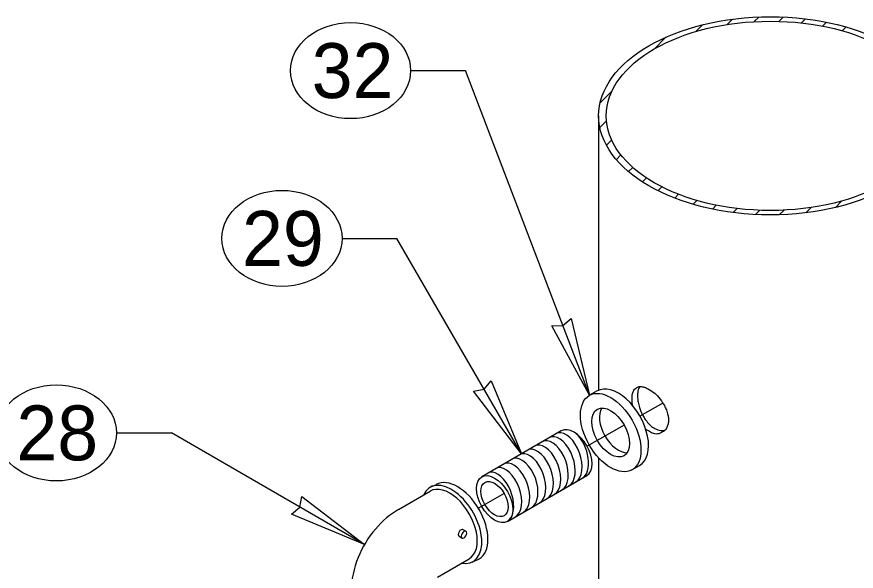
# Model space of a CAD drawing. Extents: x 99862 to 104211, y 98939 to 102076.
# Drawn here: x 101491.1 to 101735.6, y 101139.5 to 101301.1 of the extents above; entities that cross this region are included whole.
import ezdxf

# ---------------------------------------------------------------- set-up
doc = ezdxf.new("R2010")
doc.units = 0
for name, color, linetype in [('Level 1', 7, 'Continuous'), ('Level 12', 7, 'Continuous'), ('Level 15', 7, 'Continuous'), ('Level 16', 7, 'Continuous'), ('Level 2', 7, 'Continuous'), ('Level 20', 7, 'Continuous'), ('Level 28', 7, 'Continuous'), ('Level 29', 7, 'Continuous'), ('Level 30', 7, 'Continuous')]:
    doc.layers.add(name, color=color, linetype=linetype)

msp = doc.modelspace()

# ---------------------------------------------------------------- linework, layer by layer
at = {"layer": 'Level 1'}
msp.add_line((101671.69, 101193.07), (101671.69, 101193.07), dxfattribs=at)
for major_axis in [(50, 0), (47.77, 0)]:
    msp.add_ellipse((101710.6, 101272.27), major_axis=major_axis, ratio=0.57735, dxfattribs=at)
for centre, start_param, end_param in [((101650.96, 101172.59), 3.242095, 6.183178), ((101652.84, 101173.67), 3.242095, 5.457347), ((101646.93, 101170.26), 3.242095, 6.183178), ((101648.96, 101171.43), 3.242095, 6.183178), ((101642.6, 101167.76), 3.242095, 6.183178), ((101644.73, 101168.99), 3.242095, 6.183178), ((101638.1, 101165.16), 3.242095, 6.183178), ((101640.36, 101166.46), 3.242095, 6.183178), ((101633.35, 101162.42), 3.242095, 6.183178), ((101635.68, 101163.76), 3.242095, 6.183178), ((101631.03, 101161.08), 3.397612, 6.183178), ((101631.03, 101161.08), 3.242095, 3.243786)]:
    msp.add_ellipse(centre, major_axis=(-2.6, 7.2), ratio=0.565545, start_param=start_param, end_param=end_param, dxfattribs=at)
for points in [[(101670.54, 101187.8), (101670.41, 101188.48), (101670.34, 101189.14), (101670.34, 101190.55), (101670.45, 101191.26), (101670.91, 101192.39), (101671.25, 101192.81), (101672.13, 101193.32), (101672.66, 101193.4), (101673.87, 101193.24), (101674.55, 101192.98), (101676.62, 101191.78), (101678.1, 101190.38), (101679.73, 101187.93), (101680.17, 101187.05), (101680.78, 101185.3), (101680.94, 101184.44), (101680.94, 101182.82), (101680.78, 101182.09), (101680.18, 101180.87), (101679.73, 101180.39), (101678.11, 101179.45), (101676.64, 101179.52), (101675.24, 101180.33), (101674.92, 101180.52), (101674.62, 101180.73), (101674.32, 101180.98)], [(101672.6, 101193.34), (101672.17, 101192.72), (101671.94, 101191.79), (101671.94, 101189.88), (101672.05, 101188.98), (101672.5, 101187.14), (101672.84, 101186.21), (101673.72, 101184.44), (101674.25, 101183.62), (101675.45, 101182.22), (101676.13, 101181.65), (101677.87, 101180.64), (101678.97, 101180.45), (101679.92, 101180.66)]]:
    msp.add_open_spline(points, degree=3, dxfattribs=at)
at = {"layer": 'Level 12'}
for p, q in [((101698.03, 101298.88), (101699.58, 101300.43)), ((101705.94, 101299.72), (101707.27, 101301.05)), ((101713.11, 101299.81), (101714.33, 101301.04)), ((101719.71, 101299.35), (101720.87, 101300.5)), ((101725.84, 101298.41), (101726.97, 101299.53)), ((101688.93, 101296.85), (101690.87, 101298.79)), ((101731.56, 101297.05), (101732.65, 101298.15)), ((101676.73, 101291.72), (101680.18, 101295.17)), ((101661.08, 101276.07), (101664.49, 101279.48)), ((101660.6, 101272.27), (101660.6, 101192.31)), ((101660.99, 101268.91), (101662.9, 101270.82)), ((101662.89, 101263.74), (101664.4, 101265.25)), ((101665.76, 101259.54), (101667.1, 101260.88)), ((101669.31, 101256.02), (101670.54, 101257.25)), ((101673.39, 101253.03), (101674.55, 101254.18)), ((101677.9, 101250.47), (101679.02, 101251.58)), ((101682.8, 101248.29), (101683.91, 101249.4)), ((101688.1, 101246.52), (101689.2, 101247.62)), ((101693.76, 101245.11), (101694.88, 101246.23)), ((101720.97, 101244.04), (101722.5, 101245.57)), ((101729.57, 101245.57), (101731.47, 101247.47)), ((101699.83, 101244.11), (101700.98, 101245.26)), ((101706.32, 101243.53), (101707.54, 101244.75)), ((101713.33, 101243.47), (101714.66, 101244.8)), ((101660.6, 101172.62), (101660.6, 100999.47))]:
    msp.add_line(p, q, dxfattribs=at)
at = {"layer": 'Level 15'}
for p, q in [((101605.83, 101285.45), (101621.83, 101285.45)), ((101657.92, 101190.82), (101621.83, 101285.45)), ((101585.85, 101236.55), (101601.85, 101236.55)), ((101638.11, 101173.74), (101601.85, 101236.55)), ((101679.31, 101188.55), (101672.64, 101184.74)), ((101668.08, 101182.13), (101657.26, 101175.95)), ((101520.12, 101179.86), (101536.12, 101179.86)), ((101592.41, 101147.36), (101536.12, 101179.86)), ((101633.1, 101162.19), (101625.57, 101157.89))]:
    msp.add_line(p, q, dxfattribs=at)
for points in [[(101657.92, 101190.82), (101647, 101211.08), (101650.16, 101211.16), (101652.58, 101213.21)], [(101638.11, 101173.74), (101624.11, 101192.02), (101627.22, 101192.6), (101629.28, 101195)], [(101592.41, 101147.36), (101571.15, 101156.19), (101573.56, 101158.25), (101574.13, 101161.36)]]:
    msp.add_lwpolyline(points, close=True, dxfattribs=at)
at = {"layer": 'Level 16'}
for p, q in [((101621.07, 101151.68), (101621.93, 101151.18)), ((101619.94, 101149.72), (101620.81, 101149.22))]:
    msp.add_line(p, q, dxfattribs=at)
msp.add_ellipse((101620.51, 101150.7), major_axis=(-0.566, -0.98), ratio=0.57735, start_param=3.150736, end_param=6.274144, dxfattribs=at)
at = {"layer": 'Level 2'}
msp.add_ellipse((101621.37, 101150.2), major_axis=(-0.566, -0.98), ratio=0.57735, start_param=0.009244, end_param=6.292227, dxfattribs=at)
at = {"layer": 'Level 20'}
for centre in [(101588.33, 101285.45), (101568.35, 101236.55), (101502.62, 101179.86)]:
    msp.add_ellipse(centre, major_axis=(-17.5, 0), ratio=0.8, dxfattribs=at)
at = {"layer": 'Level 28'}
for p, q in [((101660.14, 101192.08), (101657.92, 101190.82)), ((101670.32, 101169.11), (101672.54, 101170.37))]:
    msp.add_line(p, q, dxfattribs=at)
for major_axis, start_param, end_param in [((6.2, -10.85), 0, 3.141593), ((3.88, -6.78), 3.428349, 5.996429)]:
    msp.add_ellipse((101666.34, 101181.23), major_axis=major_axis, ratio=0.57735, start_param=start_param, end_param=end_param, dxfattribs=at)
for major_axis in [(-6.2, 10.85), (-3.88, 6.78)]:
    msp.add_ellipse((101664.12, 101179.96), major_axis=major_axis, ratio=0.57735, dxfattribs=at)
at = {"layer": 'Level 29'}
for p, q in [((101611.52, 101164.01), (101613.32, 101164.82)), ((101602.25, 101157.52), (101611.54, 101162.88)), ((101613.62, 101137.84), (101622.91, 101143.2)), ((101623.72, 101142.2), (101625.8, 101143.17))]:
    msp.add_line(p, q, dxfattribs=at)
for centre, major_axis, start_param, end_param in [((101617.72, 101153.16), (6.25, -10.83), 5.825287, 9.824426), ((101619.5, 101153.96), (6.25, -10.83), 0.007997, 3.131655), ((101617.22, 101153.04), (5.68, -9.84), 6.283185, 9.424778)]:
    msp.add_ellipse(centre, major_axis=major_axis, ratio=0.57735, start_param=start_param, end_param=end_param, dxfattribs=at)
msp.add_open_spline([(101602.25, 101157.52), (101599.93, 101156.18), (101595.27, 101152.26), (101590, 101143.77), (101588.54, 101137.08), (101588.54, 101133.76)], degree=3, dxfattribs=at)
at = {"layer": 'Level 30'}
for p, q in [((101649.68, 101180.42), (101626.54, 101167.06)), ((101634.04, 101154.07), (101657.18, 101167.43))]:
    msp.add_line(p, q, dxfattribs=at)
msp.add_ellipse((101653.43, 101173.93), major_axis=(-3.75, 6.5), ratio=0.57735, start_param=3.141593, end_param=6.283185, dxfattribs=at)
for major_axis in [(-3.75, 6.5), (-2.81, 4.87)]:
    msp.add_ellipse((101630.29, 101160.57), major_axis=major_axis, ratio=0.57735, dxfattribs=at)

# ---------------------------------------------------------------- texts
at = {"layer": 'Level 20'}
for s, p in [('32', (101577.01, 101277.45)), ('29', (101556.72, 101228.55)), ('28', (101490.99, 101171.86))]:
    msp.add_text(s, height=16, dxfattribs=at).set_placement(p)

doc.saveas('drawing.dxf')
